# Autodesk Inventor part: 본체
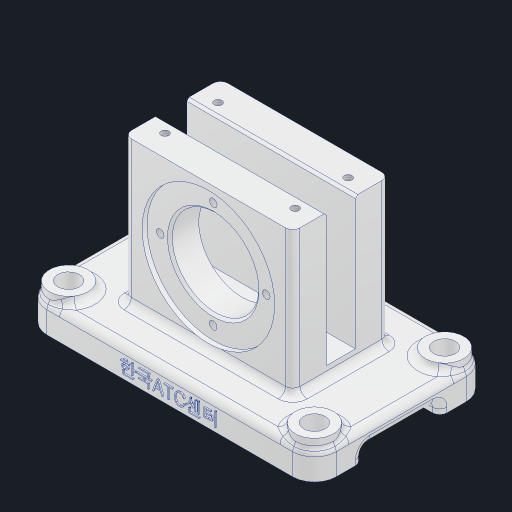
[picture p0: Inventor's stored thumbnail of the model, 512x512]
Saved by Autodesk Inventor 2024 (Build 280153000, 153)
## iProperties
Created: 2025-04
Part Number: 본체
Material: 알루미늄 6061
Document SubType Name: Modeling
Designer: kh_501
Density: 2.7 g/cm^3
Appearance: 알루미늄 - 평지
Mass: 493.657 g
Surface Area: 439.689 cm^2
Volume: 182.836 cm^3
Author: kh_501
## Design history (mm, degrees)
sketch "스케치1"
  geometry: L1 (-36, 60)-(36, 60); L2 (36, 60)-(36, -60); L3 (36, -60)-(-36, -60); L4 (-36, -60)-(-36, 60); L5 (-36, 60)-(36, -60); L6 (36, 60)-(-36, -60); 1 further point
  constraints: 12 end point, 2 midpoint, 2 parallel, 1 horizontal, 1 perpendicular
  dimensions: "d0" = 72 distance of L2.end L3.end; "d1" = 120 distance of L1.end L2.end
extrude "돌출1" new body sketch "스케치1" distance "d2" = 12; taper "d3" = 0 deg
sketch "스케치2"
  geometry: L1 (20, -35)-(-20, -35); L2 (-20, -35)-(-20, 35); L3 (-20, 35)-(20, 35); L4 (20, 35)-(20, -35); L5 (20, -35)-(-20, 35); L6 (-20, -35)-(20, 35); 1 further point
  constraints: 12 end point, 2 midpoint, 2 parallel, 1 horizontal, 1 perpendicular
  dimensions: "d4" = 40 distance of L2.end L3.end; "d5" = 70 distance of L1.end L2.end
extrude "돌출2" join sketch "스케치2" distance "d6" = 60; taper "d7" = 0 deg
sketch "스케치3"
  geometry: L1 (6, -35)-(-6, -35); L2 (-6, -35)-(-6, 35); L3 (-6, 35)-(6, 35); L4 (6, 35)-(6, -35); L5 (6, -35)-(-6, 35); L6 (-6, -35)-(6, 35); 1 further point
  constraints: 12 end point, 2 midpoint, 2 parallel, 1 horizontal, 1 perpendicular
  dimensions: "d8" = 12 distance of L2.end L3.end; "d9" = 70 distance of L1.end L2.end
extrude "돌출3" cut sketch "스케치3" distance "d10" = 55; taper "d11" = 0 deg
fillet "모깎기1" dims "d12" = 9
sketch "스케치4"
  geometry: C1 r 8 at (-27, -51); C2 r 8 at (27, -51); C3 r 8 at (27, 51); C4 r 8 at (-27, 51); 5 further points
  constraints: 4 centre point, 4 coincident, 2 horizontal alignment, 2 vertical alignment
  dimensions: "d13" = 102 distance of point (-27, 51) point (-27, -51); "d14" = 51 vertical distance of point (0, 0) point (-27, -51) (= 0.5 x d13); "d15" = 54 distance of point (27, -51) point (-27, -51); "d16" = 27 horizontal distance of point (0, 0) point (-27, -51) (= 0.5 x d15); "d17" = 16 diameter of C1; "d18" = 16 diameter of C2; "d19" = 16 diameter of C3; "d20" = 16 diameter of C4
extrude "돌출4" join sketch "스케치4" distance "d21" = 3; taper "d22" = 0 deg
sketch "스케치5"
  geometry: C1 r 8 at (-54, 0) reference; C2 r 8 at (0, 0) reference; C3 r 8 at (0, 102) reference; C4 r 8 at (-54, 102) reference; 5 further points
  constraints: 4 coincident
hole "구멍1" sketch "스케치5" at (-54, 0), (0, 0), (0, 102), (-54, 102) diameter "d23" = 9; stored, may be unused: countersink angle "d27" = 90 deg, drill point angle "d29" = 118 deg; dims "d24" = 12, "d25" = 4, "d26" = 2, "d28" = 15
sketch "스케치6"
  geometry: L1 (20, 12)-(20, 72) reference; L2 (20, 42)-(-27, 42); L3 (-22.5, 0)-(-31.5, 0) reference; L4 (20, 69.5)-(18, 69.5); L5 (18, 69.5)-(18, 60); L6 (18, 60)-(-6, 60); L7 (-6, 60)-(-6, 57); L8 (-6, 57)-(-11, 57); L9 (-11, 57)-(-11, 53); L10 (-11, 53)-(-27, 53); L11 (-27, 53)-(-27, 42); L12 (-6, 17)-(-6, 72) reference; L13 (-20, 12)-(-20, 72) reference; L14 (-20, 59)-(-27, 59); L15 (-27, 59)-(-27, 53); 2 further points
  constraints: 22 end point, 8 perpendicular, 3 horizontal, 3 point on line, 1 midpoint
  dimensions: "d30" = 47 distance of L2.start L2.end; "d31" = 42 distance between parallel lines of L3 L2; "d32" = 22 diameter of L10 L2; "d33" = 5 distance of L7.end L8.end; "d34" = 2 distance of L4.start L4.end; "d35" = 36 diameter of L6 L2; "d36" = 30 diameter of L8 L2; "d37" = 55 diameter of L4 L2; "d38" = 34 diameter of L14 L2
revolve "회전1" stored, may be unused: angle "d39" = 90 deg
revolve "회전2" stored, may be unused: angle "d40" = 90 deg
sketch "스케치7" dims "d41" = 44
  geometry: L1 (0, 0)-(0, 27.5); 3 further points
  constraints: 2 end point, 2 vertical alignment, 1 point on line, 1 vertical, 3 other
hole "구멍2" sketch "스케치7" at (0, 22) diameter "d42" = 3.242; stored, may be unused: countersink angle "d46" = 90 deg, drill point angle "d48" = 118 deg; dims "d43" = 8, "d44" = 4, "d45" = 2, "d47" = 10
sketch "스케치8"
  geometry: 5 further points
  constraints: 2 horizontal alignment, 2 vertical alignment
  dimensions: "d52" = 54 distance of point (-11, 27) point (-11, -27); "d53" = 22 distance of point (11, 27) point (-11, 27); "d54" = 27 vertical distance of point (0, 0) point (-11, -27) (= 0.5 x d52); "d55" = 11 horizontal distance of point (11, 27) point (0, 0) (= 0.5 x d53)
hole "구멍3" sketch "스케치8" at (-11, -27), (-11, 27), (11, 27), (11, -27) diameter "d56" = 3.242; stored, may be unused: countersink angle "d60" = 90 deg, drill point angle "d62" = 118 deg; dims "d57" = 8, "d58" = 4, "d59" = 2, "d61" = 10
fillet "모깎기2" dims "d63" = 3
fillet "모깎기3" dims "d64" = 3
chamfer "모따기1" distance "d65" = 1; stored, may be unused: second distance "d66" = 2, angle "d67" = 45 deg
sketch "스케치9"
  geometry: L1 (11, 0)-(43, 0); L2 (43, 0)-(43, 5); L3 (43, 5)-(11, 5); L4 (11, 5)-(11, 0); L5 (11, 0)-(43, 5); L6 (43, 0)-(11, 5); L7 (0, 0)-(54, 0) reference; 3 further points
  constraints: 12 end point, 4 midpoint, 2 parallel, 1 horizontal, 1 perpendicular
  dimensions: "d68" = 32 distance of L3.end L2.end; "d69" = 5 distance of L2.end L1.end
extrude "돌출5" cut sketch "스케치9" extent not by distance; stored distance "d70" = 0; taper "d71" = 0 deg
fillet "모깎기4" dims "d72" = 3
sketch "스케치10" dims "d0" = 72, "d1" = 120
  geometry: L1 (0, 0)-(102, 0) reference; 4 further points
  constraints: 2 midpoint, 1 vertical alignment, 1 other
  dimensions: "d73" = 5 distance of point (51, 0) point (51, 5)
feature "엠보싱1" sketch "스케치10" dims "d0" = 72, "d1" = 120, "d8" = 12, "d74" = 0.5, "d75" = 0
node "솔리드1"
pattern_circular "원형 패턴1" dims angle "d50" = 360 deg
feature "A9D066F2-1C7D-4E18-AEED-F7BC21143FA4" dims "d23" = 9, "d24" = 12, "d25" = 4, "d26" = 2, "d27" = 90 deg, "d28" = 15, "d29" = 118 deg
